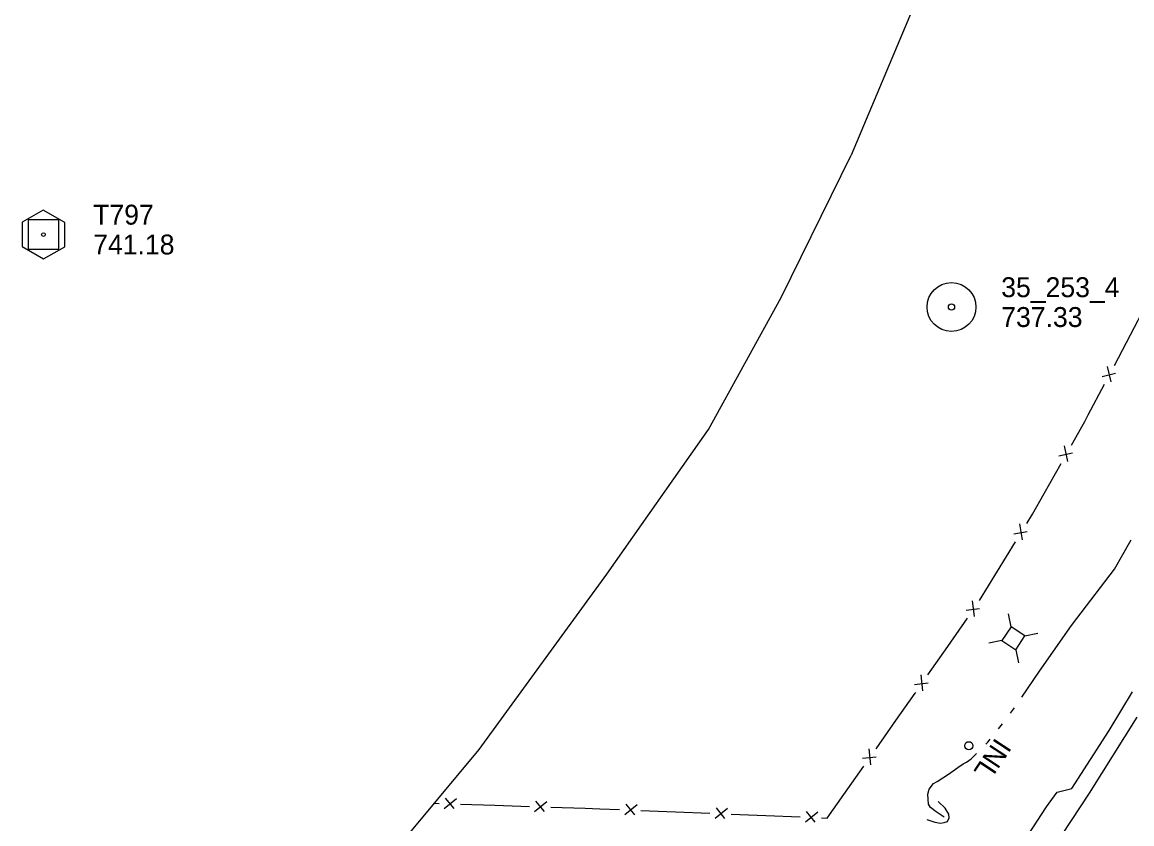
# Model space of a CAD drawing. Extents: x 589250 to 1188077, y 162953 to 363065.
# Drawn here: x 593652.9 to 593987.7, y 166441.6 to 166683.4 of the extents above; entities that cross this region are included whole.
import ezdxf

# ---------------------------------------------------------------- set-up
doc = ezdxf.new("R2010")
doc.units = 0
for name, color, linetype in [('E_DRN', 7, 'Continuous'), ('E_DRN_Text', 7, 'Continuous'), ('E_FEN_P', 7, 'Continuous'), ('E_MAP_Control', 7, 'Continuous'), ('E_MAP_Limits', 7, 'Continuous'), ('E_MAP_PassPoints', 7, 'Continuous'), ('E_RDWY', 7, 'Continuous'), ('E_RDWY_Gravel', 7, 'Continuous'), ('E_UTL_AG_Bold', 7, 'Continuous'), ('E_WAL', 7, 'Continuous'), ('E_WTR_FlowLine', 7, 'Continuous')]:
    doc.layers.add(name, color=color, linetype=linetype)

msp = doc.modelspace()

# ---------------------------------------------------------------- linework, layer by layer
at = {"layer": 'E_DRN'}
msp.add_circle((593938.56, 166465.16), 1.23, dxfattribs=at)
at = {"layer": 'E_FEN_P'}
for p, q in [((593987.33, 166589.1), (593992.12, 166598.21)), ((593982.48, 166579.89), (593987.33, 166589.1)), ((593978.79, 166576.54), (593982.8, 166577.52)), ((593981.51, 166574.93), (593980.41, 166579.61)), ((593974.62, 166564.98), (593979.47, 166574.19)), ((593973.56, 166562.96), (593974.62, 166564.98)), ((593969.56, 166555.88), (593973.56, 166562.96)), ((593965.77, 166552.65), (593969.81, 166553.5)), ((593968.44, 166550.95), (593967.48, 166555.66)), ((593961.25, 166541.21), (593966.38, 166550.27)), ((593957.76, 166535.04), (593961.25, 166541.21)), ((593956.02, 166532.21), (593957.76, 166535.04)), ((593954.73, 166527.32), (593953.94, 166532.06)), ((593947.2, 166517.85), (593952.65, 166526.72)), ((593952.13, 166529.12), (593956.19, 166529.82)), ((593941.74, 166508.98), (593947.2, 166517.85)), ((593940.24, 166504.13), (593939.71, 166508.91)), ((593932.18, 166495.1), (593938.12, 166503.65)), ((593937.74, 166506.07), (593941.83, 166506.55)), ((593926.24, 166486.55), (593932.18, 166495.1)), ((593924.68, 166481.74), (593924.15, 166486.52)), ((593922.18, 166483.68), (593926.27, 166484.15)), ((593916.57, 166472.75), (593922.39, 166481.01)), ((593922.39, 166481.01), (593922.56, 166481.26)), ((593910.57, 166464.24), (593916.57, 166472.75)), ((593908.97, 166459.44), (593908.48, 166464.22)), ((593906.48, 166461.39), (593910.58, 166461.84)), ((593900.85, 166450.46), (593906.85, 166458.97)), ((593895.85, 166443.36), (593900.85, 166450.46)), ((593777.26, 166447.8), (593778.69, 166447.75)), ((593780.24, 166446.24), (593783.97, 166449.28)), ((593780.51, 166449.39), (593783.14, 166446.21)), ((593785.13, 166447.54), (593795.54, 166447.2)), ((593795.54, 166447.2), (593805.94, 166446.85)), ((593807.5, 166445.34), (593811.22, 166448.38)), ((593807.77, 166448.49), (593810.39, 166445.31)), ((593812.38, 166446.64), (593822.79, 166446.3)), ((593834.74, 166444.39), (593838.49, 166447.39)), ((593835.03, 166447.53), (593837.63, 166444.33)), ((593862.28, 166446.43), (593864.88, 166443.23)), ((593822.79, 166446.3), (593827.23, 166446.15)), ((593827.23, 166446.15), (593833.19, 166445.91)), ((593839.63, 166445.65), (593850.04, 166445.22)), ((593850.04, 166445.22), (593860.44, 166444.8)), ((593861.98, 166443.28), (593865.73, 166446.29)), ((593866.88, 166444.54), (593877.28, 166444.12)), ((593877.28, 166444.12), (593887.69, 166443.69)), ((593889.23, 166442.17), (593892.98, 166445.18)), ((593889.52, 166445.32), (593892.12, 166442.12)), ((593894.13, 166443.43), (593895.85, 166443.36))]:
    msp.add_line(p, q, dxfattribs=at)
at = {"layer": 'E_MAP_Control'}
for p, q in [((593654.8, 166614.87), (593654.8, 166623.87)), ((593654.8, 166623.87), (593663.8, 166623.87)), ((593654.8, 166614.87), (593654.8, 166623.87)), ((593654.8, 166623.87), (593663.8, 166623.87)), ((593654.8, 166614.87), (593654.8, 166623.87)), ((593654.8, 166623.87), (593663.8, 166623.87)), ((593663.8, 166623.87), (593663.8, 166614.87)), ((593663.8, 166623.87), (593663.8, 166614.87)), ((593663.8, 166623.87), (593663.8, 166614.87)), ((593663.8, 166614.87), (593654.8, 166614.87)), ((593663.8, 166614.87), (593654.8, 166614.87)), ((593663.8, 166614.87), (593654.8, 166614.87))]:
    msp.add_line(p, q, dxfattribs=at)
msp.add_lwpolyline([(593652.89, 166623.13), (593652.89, 166615.74), (593659.35, 166612.02), (593665.75, 166615.68), (593665.75, 166623.01), (593659.23, 166626.73)], close=True, dxfattribs=at)
msp.add_lwpolyline([(593652.89, 166623.13), (593652.89, 166615.74), (593659.35, 166612.02), (593665.75, 166615.68), (593665.75, 166623.01), (593659.23, 166626.73)], close=True, dxfattribs=at)
msp.add_lwpolyline([(593652.89, 166623.13), (593652.89, 166615.74), (593659.35, 166612.02), (593665.75, 166615.68), (593665.75, 166623.01), (593659.23, 166626.73)], close=True, dxfattribs=at)
msp.add_circle((593659.3, 166619.37), 0.546, dxfattribs=at)
msp.add_circle((593659.3, 166619.37), 0.546, dxfattribs=at)
msp.add_circle((593659.3, 166619.37), 0.546, dxfattribs=at)
at = {"layer": 'E_MAP_Limits'}
for p, q in [((593924.59, 166694.46), (593903.03, 166643.32)), ((593881.92, 166600.34), (593903.03, 166643.32)), ((593859.96, 166560.56), (593881.92, 166600.34)), ((593829.37, 166516.9), (593859.96, 166560.56)), ((593790.77, 166464.02), (593829.37, 166516.9)), ((593748.01, 166412.68), (593790.77, 166464.02))]:
    msp.add_line(p, q, dxfattribs=at)
at = {"layer": 'E_MAP_PassPoints'}
for radius in [7.38, 7.38, 7.38, 0.945, 0.945, 0.945]:
    msp.add_circle((593933.34, 166597.51), radius, dxfattribs=at)
at = {"layer": 'E_RDWY'}
for p, q in [((593989.24, 166473.76), (593974.83, 166450.81)), ((593974.83, 166450.81), (593959.36, 166427.37))]:
    msp.add_line(p, q, dxfattribs=at)
at = {"layer": 'E_RDWY_Gravel'}
for p, q in [((593980.89, 166469.78), (593987.92, 166481.46)), ((593969.67, 166452.29), (593980.89, 166469.78)), ((593962, 166446.69), (593965.27, 166451.15)), ((593965.27, 166451.15), (593969.67, 166452.29)), ((593948.82, 166426.63), (593962, 166446.69))]:
    msp.add_line(p, q, dxfattribs=at)
at = {"layer": 'E_UTL_AG_Bold'}
for p, q in [((593951.31, 166501.07), (593950.51, 166504.99)), ((593951.31, 166501.07), (593948.55, 166496.9)), ((593955.48, 166498.3), (593951.31, 166501.07)), ((593948.55, 166496.9), (593944.63, 166496.1)), ((593948.55, 166496.9), (593952.72, 166494.14)), ((593952.72, 166494.14), (593955.48, 166498.3)), ((593955.48, 166498.3), (593959.4, 166499.1)), ((593952.72, 166494.14), (593953.51, 166490.22))]:
    msp.add_line(p, q, dxfattribs=at)
at = {"layer": 'E_WAL'}
for p, q in [((593931.44, 166446.33), (593929.33, 166448.37)), ((593932.53, 166444.54), (593931.44, 166446.33)), ((593932.1, 166442.26), (593932.62, 166443.41)), ((593932.62, 166443.41), (593932.53, 166444.54)), ((593925.88, 166442.9), (593928.29, 166442.14)), ((593928.29, 166442.14), (593929.97, 166441.83)), ((593929.97, 166441.83), (593931.17, 166441.98)), ((593931.17, 166441.98), (593932.1, 166442.26))]:
    msp.add_line(p, q, dxfattribs=at)
at = {"layer": 'E_WTR_FlowLine'}
for p, q in [((593982.51, 166518.42), (593987.57, 166527.23)), ((593971.14, 166503.53), (593982.51, 166518.42)), ((593969.54, 166501.44), (593971.14, 166503.53)), ((593959.87, 166487.65), (593969.54, 166501.44)), ((593954.6, 166479.85), (593959.87, 166487.65)), ((593951.17, 166474.96), (593952.32, 166476.58)), ((593947.51, 166470.23), (593948.73, 166471.8)), ((593944.3, 166466.22), (593945.02, 166467.12)), ((593943.72, 166465.62), (593944.3, 166466.22)), ((593936.85, 166459.68), (593937.85, 166460.17)), ((593937.85, 166460.17), (593939.23, 166461.19)), ((593939.23, 166461.19), (593940.92, 166462.78)), ((593929.05, 166454.41), (593932.42, 166456.6)), ((593932.42, 166456.6), (593935.26, 166458.59)), ((593935.26, 166458.59), (593936.85, 166459.68)), ((593926.61, 166452.1), (593927.86, 166453.73)), ((593927.86, 166453.73), (593929.05, 166454.41)), ((593926.23, 166450.56), (593926.61, 166452.1)), ((593926.26, 166449.02), (593926.23, 166450.56)), ((593926.35, 166447.49), (593926.26, 166449.02)), ((593927.03, 166446.49), (593926.35, 166447.49)), ((593928.73, 166445.25), (593927.03, 166446.49)), ((593931.16, 166443.62), (593928.73, 166445.25))]:
    msp.add_line(p, q, dxfattribs=at)

# ---------------------------------------------------------------- texts
at = {"layer": 'E_DRN_Text'}
msp.add_text('INL', height=6, rotation=236.4767, dxfattribs=at).set_placement((593946.71, 166467.86))
at = {"layer": 'E_MAP_Control'}
for s, p in [('T797', (593674.31, 166622.37)), ('T797', (593674.31, 166622.37)), ('T797', (593674.31, 166622.37)), ('741.18', (593674.31, 166613.37)), ('741.18', (593674.31, 166613.37)), ('741.18', (593674.31, 166613.37))]:
    msp.add_text(s, height=6, dxfattribs=at).set_placement(p)
at = {"layer": 'E_MAP_PassPoints'}
for s, p in [('35_253_4', (593948.34, 166600.49)), ('35_253_4', (593948.34, 166600.49)), ('35_253_4', (593948.34, 166600.49)), ('737.33', (593948.34, 166591.49)), ('737.33', (593948.34, 166591.49)), ('737.33', (593948.34, 166591.49))]:
    msp.add_text(s, height=6, dxfattribs=at).set_placement(p)

doc.saveas('drawing.dxf')
